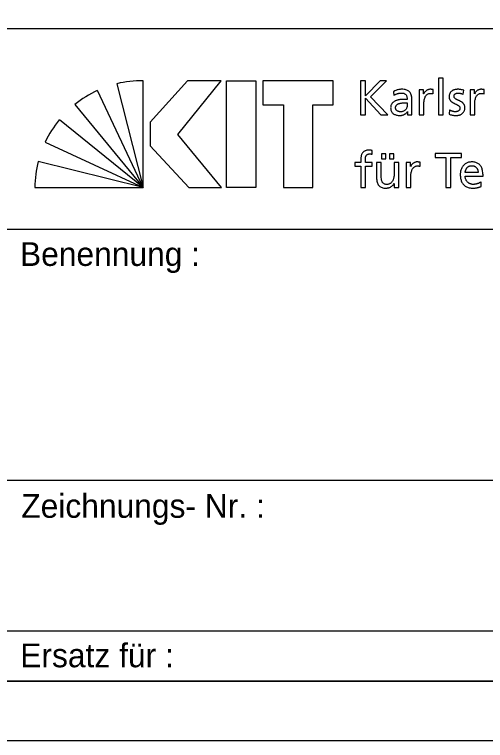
# Model space of a CAD drawing. Extents: x 0 to 238, y 0 to 168.
# Drawn here: x 220.13 to 228.07, y 0 to 12.23 of the extents above; entities that cross this region are included whole.
import ezdxf

# ---------------------------------------------------------------- set-up
doc = ezdxf.new("R2010")
doc.units = 0
doc.layers.add('90_Plankopf', color=7, linetype='Continuous')

msp = doc.modelspace()

# ---------------------------------------------------------------- linework, layer by layer
at = {"layer": '90_Plankopf'}
for p, q in [((201.224, 11.998), (236.8, 11.998)), ((201.224, 11.998), (236.8, 11.998)), ((221.855, 11.067), (222.296, 9.317)), ((222.296, 9.317), (222.296, 11.117)), ((225.962, 11.117), (225.962, 10.541)), ((222.296, 9.317), (221.527, 10.95)), ((226.516, 10.932), (226.52, 10.866)), ((227.185, 10.897), (227.185, 10.966)), ((227.691, 10.888), (227.698, 10.956)), ((228.042, 10.897), (228.042, 10.966)), ((226.824, 10.624), (226.824, 10.798)), ((221.149, 10.717), (222.296, 9.317)), ((226.746, 10.742), (226.746, 10.705)), ((225.962, 10.541), (226.044, 10.541)), ((226.301, 10.541), (226.422, 10.541)), ((227.459, 10.624), (227.455, 10.554)), ((222.296, 9.317), (220.887, 10.457)), ((220.648, 10.083), (222.296, 9.317)), ((226.155, 9.879), (226.158, 9.941)), ((222.296, 9.317), (220.532, 9.758)), ((226.965, 9.673), (226.965, 9.742)), ((227.941, 9.568), (227.723, 9.568)), ((227.723, 9.51), (228.024, 9.51)), ((220.473, 9.317), (222.296, 9.317)), ((227.992, 9.335), (227.992, 9.412)), ((220, 8.614), (236.8, 8.614)), ((220, 4.384), (236.8, 4.384)), ((220, 1.846), (236.8, 1.846)), ((236.8, 1), (201.224, 1)), ((203.56, 1), (236.8, 1)), ((203.56, 1), (236.8, 1))]:
    msp.add_line(p, q, dxfattribs=at)
for points in [[(0, 0), (237.8, 0), (237.8, 168.2), (0, 168.2)], [(5, 1), (236.8, 1), (236.8, 167.2), (5, 167.2)], [(223.613, 11.117), (223.047, 11.117), (222.415, 10.42), (222.415, 10.018), (223.068, 9.317), (223.617, 9.317), (222.884, 10.213)], [(224.194, 11.117), (224.194, 9.317), (223.7, 9.317), (223.7, 11.117)], [(224.312, 11.117), (224.312, 10.712), (224.66, 10.712), (224.66, 9.317), (225.154, 9.317), (225.154, 10.712), (225.502, 10.712), (225.502, 11.117)]]:
    msp.add_lwpolyline(points, close=True, dxfattribs=at)
for points in [[(227.276, 10.541), (227.354, 10.541), (227.354, 11.16), (227.276, 11.16), (227.276, 10.541)], [(226.422, 10.541), (226.129, 10.845), (226.4, 11.117), (226.29, 11.117), (226.044, 10.864), (226.044, 11.117), (225.962, 11.117)], [(227.024, 10.897), (227.023, 10.897), (227.023, 10.962), (226.95, 10.962), (226.95, 10.541), (227.028, 10.541), (227.028, 10.733)], [(227.881, 10.897), (227.88, 10.897), (227.88, 10.962), (227.807, 10.962), (227.807, 10.541), (227.885, 10.541), (227.885, 10.733)], [(226.044, 10.541), (226.044, 10.823), (226.301, 10.541)], [(226.753, 10.596), (226.754, 10.596), (226.754, 10.541), (226.827, 10.541)], [(226.311, 9.885), (226.311, 9.803), (226.388, 9.803), (226.388, 9.885), (226.311, 9.885)], [(226.446, 9.885), (226.446, 9.803), (226.524, 9.803), (226.524, 9.885), (226.446, 9.885)], [(227.398, 9.317), (227.481, 9.317), (227.481, 9.821), (227.66, 9.821), (227.66, 9.893), (227.219, 9.893), (227.219, 9.821), (227.398, 9.821), (227.398, 9.317)], [(225.965, 9.777), (225.965, 9.738), (225.866, 9.738), (225.866, 9.676), (225.965, 9.676), (225.965, 9.317), (226.042, 9.317), (226.042, 9.676), (226.154, 9.676), (226.154, 9.738), (226.042, 9.738), (226.042, 9.784)], [(226.308, 9.52), (226.308, 9.738), (226.231, 9.738), (226.231, 9.488)], [(226.603, 9.317), (226.603, 9.738), (226.525, 9.738), (226.525, 9.543)], [(226.804, 9.673), (226.803, 9.673), (226.803, 9.738), (226.73, 9.738), (226.73, 9.317), (226.808, 9.317), (226.808, 9.509)], [(226.526, 9.384), (226.528, 9.384), (226.528, 9.317), (226.603, 9.317)]]:
    msp.add_lwpolyline(points, dxfattribs=at)
for centre, start, end in [((222.29, 9.211), 89.8053, 103.1895), ((222.332, 9.224), 115.0126, 128.3968), ((222.363, 9.253), 140.7898, 154.174), ((222.378, 9.288), 165.7222, 179.1064)]:
    msp.add_arc(centre, 1.906, start, end, dxfattribs=at)
for points in [[(226.824, 10.798), (226.824, 10.836), (226.818, 10.868), (226.807, 10.894), (226.795, 10.92), (226.777, 10.939), (226.752, 10.952), (226.727, 10.965), (226.694, 10.972), (226.654, 10.972), (226.628, 10.972), (226.603, 10.968), (226.58, 10.961), (226.556, 10.954), (226.535, 10.944), (226.516, 10.932)], [(226.52, 10.866), (226.531, 10.875), (226.543, 10.883), (226.556, 10.889), (226.569, 10.896), (226.583, 10.901), (226.598, 10.904), (226.613, 10.908), (226.627, 10.909), (226.642, 10.909), (226.668, 10.909), (226.688, 10.905), (226.704, 10.897), (226.719, 10.889), (226.73, 10.877), (226.736, 10.86), (226.743, 10.844), (226.746, 10.824), (226.746, 10.799)], [(227.185, 10.966), (227.18, 10.967), (227.175, 10.968), (227.17, 10.969), (227.165, 10.97), (227.16, 10.971), (227.154, 10.971), (227.148, 10.972), (227.142, 10.972), (227.134, 10.972), (227.119, 10.972), (227.105, 10.969), (227.09, 10.962), (227.076, 10.956), (227.064, 10.947), (227.052, 10.936), (227.041, 10.925), (227.031, 10.912), (227.024, 10.897)], [(227.028, 10.733), (227.028, 10.768), (227.033, 10.799), (227.042, 10.824), (227.051, 10.85), (227.065, 10.87), (227.082, 10.883), (227.099, 10.897), (227.119, 10.904), (227.142, 10.904), (227.149, 10.904), (227.156, 10.904), (227.164, 10.903), (227.171, 10.902), (227.178, 10.9), (227.185, 10.897)], [(227.698, 10.956), (227.683, 10.96), (227.667, 10.964), (227.652, 10.967), (227.636, 10.97), (227.619, 10.972), (227.601, 10.972), (227.581, 10.972), (227.561, 10.969), (227.543, 10.964), (227.525, 10.959), (227.509, 10.951), (227.496, 10.94), (227.482, 10.929), (227.472, 10.916), (227.464, 10.9), (227.457, 10.883), (227.453, 10.864), (227.453, 10.842), (227.453, 10.826), (227.456, 10.811), (227.463, 10.799), (227.469, 10.787), (227.478, 10.776), (227.489, 10.767), (227.5, 10.758), (227.512, 10.75), (227.525, 10.743), (227.538, 10.736), (227.551, 10.729), (227.563, 10.723), (227.576, 10.717), (227.588, 10.711), (227.599, 10.704), (227.61, 10.698), (227.619, 10.691), (227.625, 10.683), (227.632, 10.675), (227.635, 10.665), (227.635, 10.654), (227.635, 10.643), (227.633, 10.633), (227.628, 10.626), (227.623, 10.618), (227.617, 10.612), (227.609, 10.607), (227.601, 10.602), (227.593, 10.599), (227.583, 10.597), (227.574, 10.595), (227.565, 10.594), (227.556, 10.594), (227.548, 10.594), (227.539, 10.595), (227.528, 10.597), (227.517, 10.599), (227.505, 10.603), (227.493, 10.607), (227.481, 10.612), (227.47, 10.617), (227.459, 10.624)], [(227.455, 10.554), (227.473, 10.545), (227.492, 10.539), (227.512, 10.536), (227.531, 10.532), (227.551, 10.531), (227.571, 10.531), (227.59, 10.531), (227.608, 10.534), (227.625, 10.539), (227.643, 10.544), (227.659, 10.552), (227.673, 10.563), (227.686, 10.574), (227.697, 10.588), (227.705, 10.604), (227.714, 10.621), (227.718, 10.64), (227.718, 10.662), (227.718, 10.682), (227.714, 10.698), (227.708, 10.711), (227.701, 10.724), (227.692, 10.736), (227.682, 10.745), (227.671, 10.754), (227.659, 10.762), (227.646, 10.769), (227.633, 10.776), (227.62, 10.782), (227.607, 10.787), (227.594, 10.793), (227.582, 10.799), (227.572, 10.805), (227.561, 10.812), (227.552, 10.819), (227.545, 10.827), (227.539, 10.836), (227.536, 10.846), (227.535, 10.858), (227.536, 10.87), (227.539, 10.879), (227.546, 10.887), (227.553, 10.894), (227.562, 10.9), (227.573, 10.904), (227.584, 10.908), (227.596, 10.909), (227.61, 10.909), (227.614, 10.909), (227.62, 10.909), (227.628, 10.908), (227.635, 10.906), (227.643, 10.905), (227.651, 10.903), (227.659, 10.901), (227.667, 10.898), (227.674, 10.896), (227.681, 10.893), (227.687, 10.891), (227.691, 10.888)], [(228.042, 10.966), (228.037, 10.967), (228.032, 10.968), (228.027, 10.969), (228.022, 10.97), (228.017, 10.971), (228.011, 10.971), (228.005, 10.972), (227.999, 10.972), (227.991, 10.972), (227.976, 10.972), (227.962, 10.969), (227.947, 10.962), (227.933, 10.956), (227.921, 10.947), (227.909, 10.936), (227.898, 10.925), (227.888, 10.912), (227.881, 10.897)], [(227.885, 10.733), (227.885, 10.768), (227.89, 10.799), (227.899, 10.824), (227.908, 10.85), (227.922, 10.87), (227.939, 10.883), (227.956, 10.897), (227.976, 10.904), (227.999, 10.904), (228.006, 10.904), (228.013, 10.904), (228.021, 10.903), (228.028, 10.902), (228.035, 10.9), (228.042, 10.897)], [(226.746, 10.799), (226.736, 10.8), (226.727, 10.8), (226.718, 10.801), (226.709, 10.801), (226.7, 10.801), (226.692, 10.801), (226.683, 10.801), (226.674, 10.801), (226.664, 10.801), (226.647, 10.801), (226.63, 10.8), (226.613, 10.797), (226.595, 10.794), (226.577, 10.789), (226.56, 10.783), (226.543, 10.776), (226.528, 10.768), (226.514, 10.757), (226.5, 10.746), (226.489, 10.733), (226.481, 10.718), (226.472, 10.702), (226.468, 10.684), (226.468, 10.662), (226.468, 10.632), (226.475, 10.607), (226.488, 10.588), (226.501, 10.568), (226.519, 10.554), (226.542, 10.545), (226.565, 10.536), (226.592, 10.531), (226.622, 10.531), (226.64, 10.531), (226.656, 10.534), (226.67, 10.538), (226.684, 10.542), (226.697, 10.547), (226.707, 10.554), (226.718, 10.56), (226.727, 10.567), (226.735, 10.575), (226.742, 10.582), (226.748, 10.589), (226.753, 10.596)], [(226.746, 10.705), (226.746, 10.684), (226.742, 10.665), (226.733, 10.648), (226.724, 10.631), (226.711, 10.618), (226.693, 10.609), (226.676, 10.599), (226.654, 10.594), (226.629, 10.594), (226.62, 10.594), (226.611, 10.596), (226.602, 10.598), (226.593, 10.601), (226.584, 10.606), (226.576, 10.611), (226.569, 10.617), (226.562, 10.625), (226.558, 10.633), (226.553, 10.641), (226.551, 10.651), (226.55, 10.662), (226.551, 10.677), (226.554, 10.69), (226.562, 10.699), (226.569, 10.709), (226.578, 10.717), (226.59, 10.723), (226.601, 10.729), (226.614, 10.733), (226.627, 10.736), (226.64, 10.739), (226.653, 10.741), (226.665, 10.742), (226.677, 10.743), (226.688, 10.743), (226.697, 10.743), (226.705, 10.743), (226.713, 10.743), (226.721, 10.743), (226.73, 10.742), (226.738, 10.742), (226.746, 10.742)], [(226.827, 10.541), (226.826, 10.545), (226.826, 10.551), (226.825, 10.557), (226.825, 10.564), (226.824, 10.573), (226.824, 10.584), (226.824, 10.595), (226.824, 10.608), (226.824, 10.624)], [(226.158, 9.941), (226.15, 9.942), (226.142, 9.944), (226.134, 9.945), (226.125, 9.946), (226.116, 9.946), (226.106, 9.946), (226.078, 9.946), (226.054, 9.942), (226.036, 9.934), (226.017, 9.926), (226.003, 9.915), (225.992, 9.9), (225.982, 9.885), (225.975, 9.867), (225.971, 9.847), (225.967, 9.826), (225.965, 9.803), (225.965, 9.777)], [(226.042, 9.784), (226.042, 9.798), (226.043, 9.811), (226.045, 9.823), (226.046, 9.835), (226.05, 9.846), (226.055, 9.855), (226.06, 9.864), (226.068, 9.871), (226.078, 9.876), (226.088, 9.881), (226.101, 9.883), (226.118, 9.883), (226.124, 9.883), (226.131, 9.883), (226.138, 9.882), (226.144, 9.881), (226.15, 9.88), (226.155, 9.879)], [(226.965, 9.742), (226.96, 9.743), (226.955, 9.744), (226.95, 9.745), (226.945, 9.746), (226.94, 9.747), (226.934, 9.747), (226.928, 9.748), (226.922, 9.748), (226.914, 9.748), (226.899, 9.748), (226.885, 9.745), (226.87, 9.738), (226.856, 9.732), (226.844, 9.723), (226.832, 9.712), (226.821, 9.701), (226.811, 9.688), (226.804, 9.673)], [(226.808, 9.509), (226.808, 9.544), (226.813, 9.575), (226.822, 9.6), (226.832, 9.626), (226.845, 9.646), (226.862, 9.659), (226.879, 9.673), (226.899, 9.68), (226.922, 9.68), (226.929, 9.681), (226.936, 9.68), (226.944, 9.679), (226.951, 9.678), (226.958, 9.676), (226.965, 9.673)], [(228.024, 9.51), (228.024, 9.544), (228.021, 9.576), (228.014, 9.605), (228.008, 9.634), (227.998, 9.659), (227.984, 9.68), (227.969, 9.701), (227.95, 9.718), (227.926, 9.73), (227.902, 9.742), (227.873, 9.748), (227.838, 9.748), (227.808, 9.748), (227.781, 9.743), (227.757, 9.732), (227.733, 9.722), (227.712, 9.707), (227.695, 9.688), (227.677, 9.669), (227.664, 9.647), (227.655, 9.621), (227.646, 9.595), (227.641, 9.567), (227.641, 9.535), (227.641, 9.501), (227.645, 9.47), (227.654, 9.442), (227.662, 9.414), (227.676, 9.39), (227.694, 9.37), (227.712, 9.35), (227.734, 9.334), (227.762, 9.324), (227.789, 9.313), (227.821, 9.308), (227.859, 9.307), (227.882, 9.308), (227.901, 9.309), (227.917, 9.312), (227.933, 9.315), (227.947, 9.319), (227.959, 9.323), (227.971, 9.327), (227.982, 9.331), (227.992, 9.335)], [(227.723, 9.568), (227.725, 9.582), (227.728, 9.596), (227.733, 9.609), (227.738, 9.623), (227.744, 9.636), (227.754, 9.647), (227.762, 9.659), (227.774, 9.668), (227.787, 9.675), (227.801, 9.682), (227.817, 9.685), (227.836, 9.685), (227.853, 9.685), (227.868, 9.682), (227.881, 9.676), (227.894, 9.67), (227.905, 9.662), (227.914, 9.651), (227.923, 9.64), (227.93, 9.628), (227.934, 9.614), (227.939, 9.6), (227.941, 9.584), (227.941, 9.568)], [(226.525, 9.543), (226.525, 9.518), (226.523, 9.494), (226.518, 9.473), (226.513, 9.452), (226.505, 9.434), (226.495, 9.418), (226.484, 9.403), (226.471, 9.391), (226.455, 9.383), (226.439, 9.374), (226.419, 9.37), (226.397, 9.37), (226.375, 9.371), (226.357, 9.378), (226.344, 9.389), (226.331, 9.4), (226.322, 9.417), (226.316, 9.439), (226.311, 9.46), (226.308, 9.488), (226.308, 9.52)], [(226.231, 9.488), (226.231, 9.45), (226.236, 9.418), (226.247, 9.391), (226.259, 9.364), (226.276, 9.343), (226.299, 9.329), (226.322, 9.315), (226.352, 9.308), (226.388, 9.307), (226.408, 9.308), (226.427, 9.311), (226.445, 9.317), (226.463, 9.323), (226.479, 9.332), (226.493, 9.343), (226.507, 9.354), (226.518, 9.368), (226.526, 9.384)], [(227.992, 9.412), (227.987, 9.408), (227.98, 9.404), (227.97, 9.399), (227.961, 9.394), (227.951, 9.39), (227.939, 9.385), (227.927, 9.381), (227.914, 9.377), (227.901, 9.374), (227.888, 9.372), (227.875, 9.37), (227.862, 9.37), (227.843, 9.37), (227.826, 9.374), (227.809, 9.38), (227.793, 9.387), (227.778, 9.397), (227.765, 9.409), (227.752, 9.421), (227.742, 9.436), (227.735, 9.453), (227.727, 9.471), (227.723, 9.49), (227.723, 9.51)]]:
    msp.add_open_spline(points, degree=3, dxfattribs=at)

# ---------------------------------------------------------------- texts
for s, p in [('Benennung :', (220.223, 7.996)), ('Zeichnungs- Nr. :', (220.245, 3.752)), ('Ersatz für :', (220.228, 1.234))]:
    msp.add_text(s, height=0.4, dxfattribs=at).set_placement(p)

doc.saveas('drawing.dxf')
